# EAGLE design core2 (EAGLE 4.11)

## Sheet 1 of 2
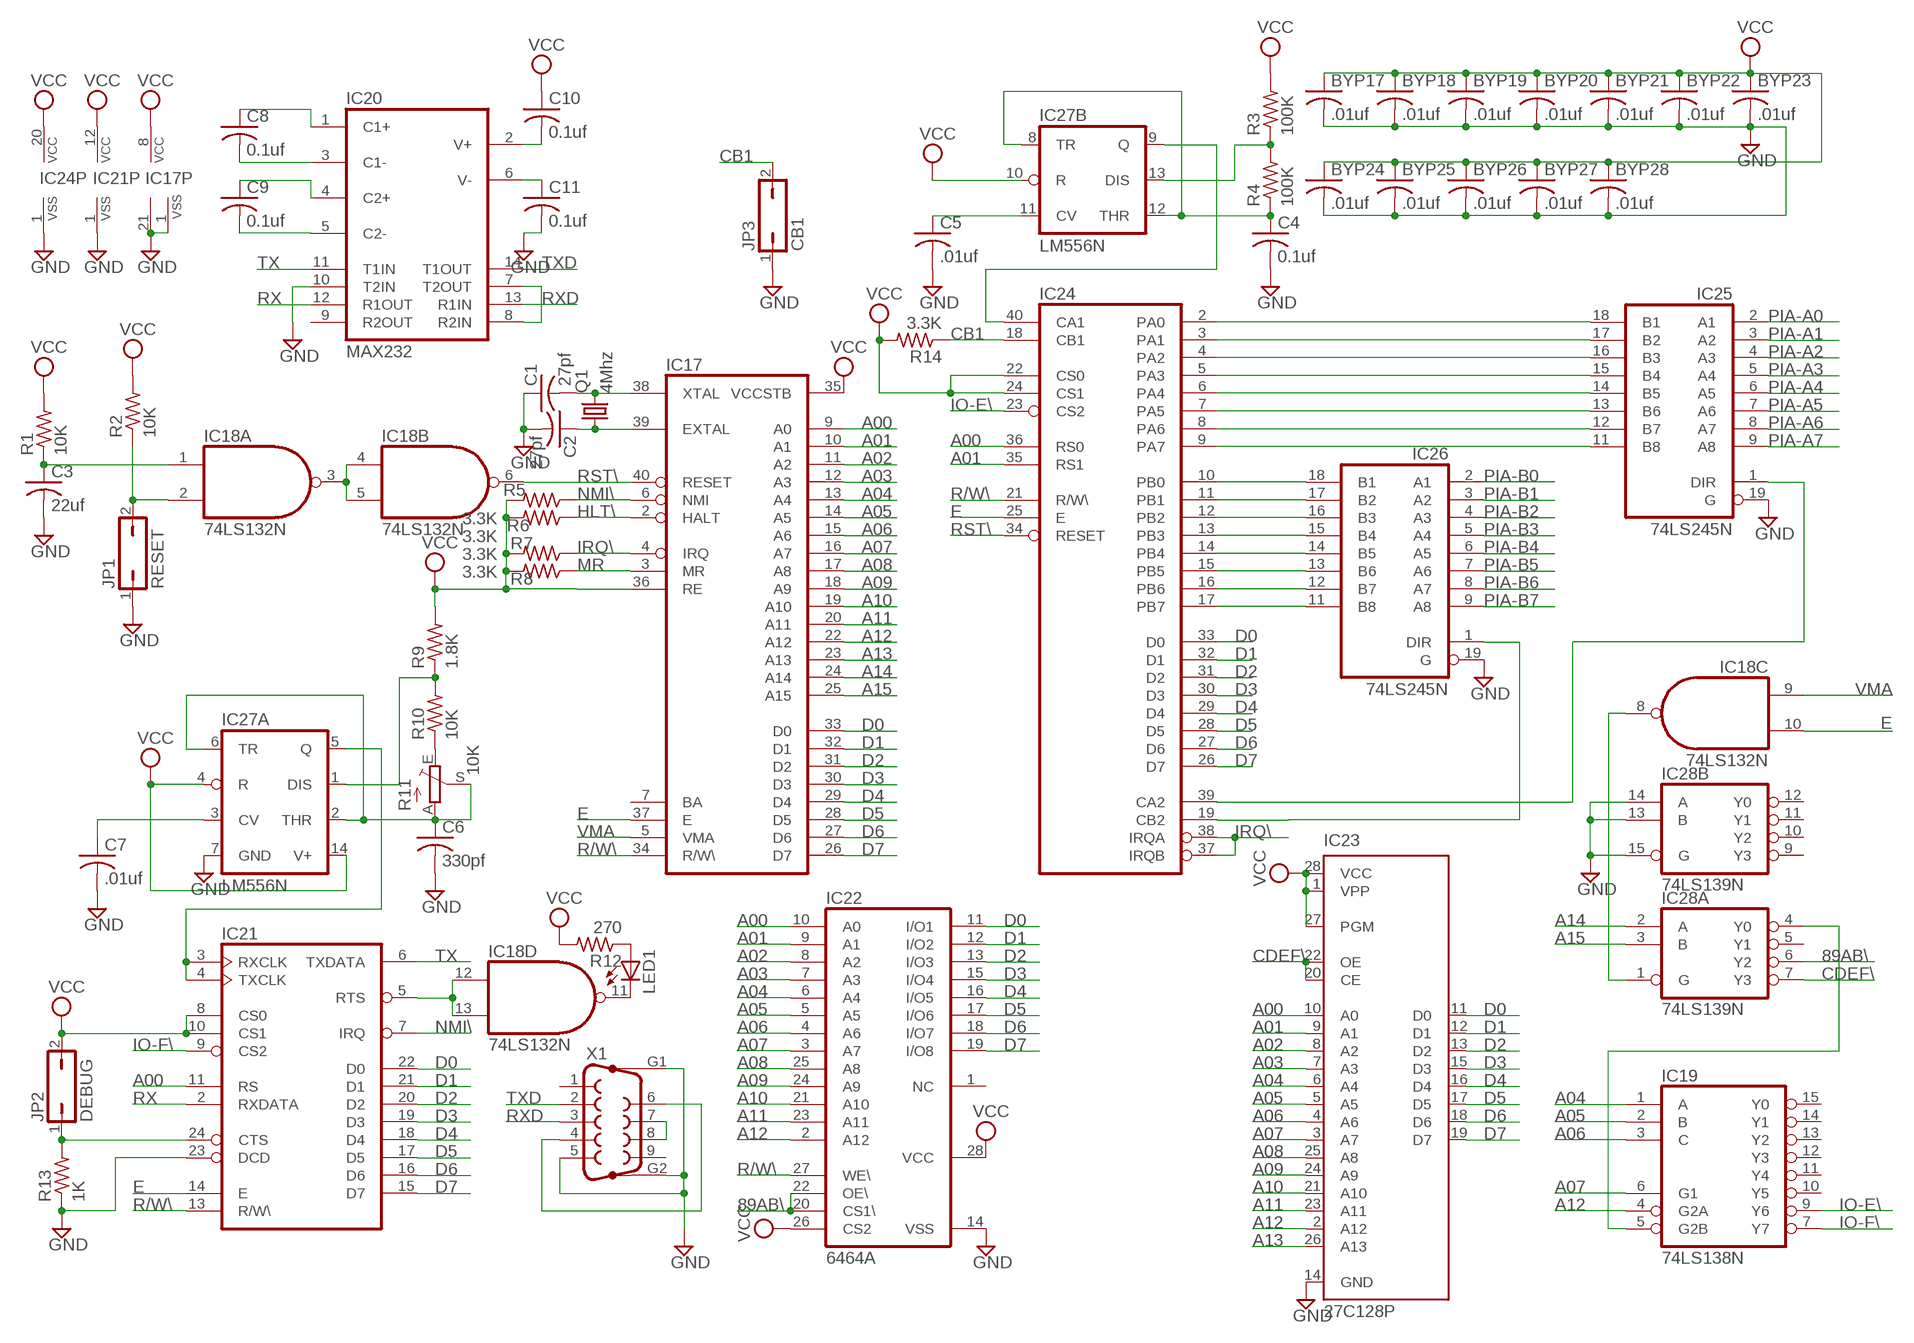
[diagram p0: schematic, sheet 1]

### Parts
BYP17  .01uf  C-US050-025X075  [C050-025X075]
BYP18  .01uf  C-US050-025X075  [C050-025X075]
BYP19  .01uf  C-US050-025X075  [C050-025X075]
BYP20  .01uf  C-US050-025X075  [C050-025X075]
BYP21  .01uf  C-US050-025X075  [C050-025X075]
BYP22  .01uf  C-US050-025X075  [C050-025X075]
BYP23  .01uf  C-US050-025X075  [C050-025X075]
BYP24  .01uf  C-US050-025X075  [C050-025X075]
BYP25  .01uf  C-US050-025X075  [C050-025X075]
BYP26  .01uf  C-US050-025X075  [C050-025X075]
BYP27  .01uf  C-US050-025X075  [C050-025X075]
BYP28  .01uf  C-US050-025X075  [C050-025X075]
C1  27pf  C-US050-025X075  [C050-025X075]
C2  27pf  C-US050-025X075  [C050-025X075]
C3  22uf  C-US102-043X133  [C102-043X133]
C4  0.1uf  C-US050-025X075  [C050-025X075]
C5  .01uf  C-US050-025X075  [C050-025X075]
C6  330pf  C-US050-025X075  [C050-025X075]
C7  .01uf  C-US050-025X075  [C050-025X075]
C8  0.1uf  C-US050-025X075  [C050-025X075]
C9  0.1uf  C-US050-025X075  [C050-025X075]
C10  0.1uf  C-US050-025X075  [C050-025X075]
C11  0.1uf  C-US050-025X075  [C050-025X075]
IC17  6802  [DIL40]
IC18  74LS132N  74LS00N  [DIL14]
IC19  74LS138N  [DIL16]
IC20  MAX232  [DIL16]
IC21  6850  [DIL24]
IC22  6464A  6264A  [DIL28-6]
IC23  27C128P  [DIL28-6]
IC24  6821  [DIL40]
IC25  74LS245N  [DIL20]
IC26  74LS245N  [DIL20]
IC27  LM556N  [DIL14]
IC28  74LS139N  [DIL16]
JP1  RESET  JP1Q  [JP1]
JP2  DEBUG  JP1Q  [JP1]
JP3  CB1  JP1Q  [JP1]
LED1  LED3MM  [LED3MM]
Q1  4Mhz  CRYTALHC18U-V  [HC18U-V]
R1  10K  R-US_0207/7  [0207/7]
R2  10K  R-US_0207/7  [0207/7]
R3  100K  R-US_0207/7  [0207/7]
R4  100K  R-US_0207/7  [0207/7]
R5  3.3K  R-US_0207/7  [0207/7]
R6  3.3K  R-US_0207/7  [0207/7]
R7  3.3K  R-US_0207/7  [0207/7]
R8  3.3K  R-US_0207/7  [0207/7]
R9  1.8K  R-US_0207/7  [0207/7]
R10  10K  R-US_0207/7  [0207/7]
R11  10K  TRIM_EU-B90P  [SP19L]
R12  270  R-US_0207/7  [0207/7]
R13  1K  R-US_0207/7  [0207/7]
R14  3.3K  R-US_0207/7  [0207/7]
X1  F09HP  [F09HP]

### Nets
89AB\: IC22.20(CS1\) IC22.22(OE\) IC28.6(A:Y2)
A00: IC17.9(A0) IC21.11(RS) IC22.10(A0) IC23.10(A0) IC24.36(RS0)
A01: IC17.10(A1) IC22.9(A1) IC23.9(A1) IC24.35(RS1)
A02: IC17.11(A2) IC22.8(A2) IC23.8(A2)
A03: IC17.12(A3) IC22.7(A3) IC23.7(A3)
A04: IC17.13(A4) IC19.1(A) IC22.6(A4) IC23.6(A4)
A05: IC17.14(A5) IC19.2(B) IC22.5(A5) IC23.5(A5)
A06: IC17.15(A6) IC19.3(C) IC22.4(A6) IC23.4(A6)
A07: IC17.16(A7) IC19.6(G1) IC22.3(A7) IC23.3(A7)
A08: IC17.17(A8) IC22.25(A8) IC23.25(A8)
A09: IC17.18(A9) IC22.24(A9) IC23.24(A9)
A10: IC17.19(A10) IC22.21(A10) IC23.21(A10)
A11: IC17.20(A11) IC22.23(A11) IC23.23(A11)
A12: IC17.22(A12) IC19.4(G2A) IC22.2(A12) IC23.2(A12)
A13: IC17.23(A13) IC23.26(A13)
A14: IC17.24(A14) IC28.2(A:A)
A15: IC17.25(A15) IC28.3(A:B)
CB1: IC24.18(CB1) JP3.2 R14.1
CDEF\: IC23.20(CE) IC23.22(OE) IC28.7(A:Y3)
D0: IC17.33(D0) IC21.22(D0) IC22.11(I/O1) IC23.11(D0) IC24.33(D0)
D1: IC17.32(D1) IC21.21(D1) IC22.12(I/O2) IC23.12(D1) IC24.32(D1)
D2: IC17.31(D2) IC21.20(D2) IC22.13(I/O3) IC23.13(D2) IC24.31(D2)
D3: IC17.30(D3) IC21.19(D3) IC22.15(I/O4) IC23.15(D3) IC24.30(D3)
D4: IC17.29(D4) IC21.18(D4) IC22.16(I/O5) IC23.16(D4) IC24.29(D4)
D5: IC17.28(D5) IC21.17(D5) IC22.17(I/O6) IC23.17(D5) IC24.28(D5)
D6: IC17.27(D6) IC21.16(D6) IC22.18(I/O7) IC23.18(D6) IC24.27(D6)
D7: IC17.26(D7) IC21.15(D7) IC22.19(I/O8) IC23.19(D7) IC24.26(D7)
E: IC17.37(E) IC18.10(C:I1) IC21.14(E) IC24.25(E)
GND [Power]: BYP17.2 BYP18.2 BYP19.2 BYP20.2 BYP21.2 BYP22.2 BYP23.2 BYP24.2 BYP25.2 BYP26.2 BYP27.2 BYP28.2 C1.1 C2.2 C3.2 C4.2 C5.2 C6.2 C7.2 C11.2 IC17.1(VSS) IC17.21(VSS) IC20.10(T2IN) IC21.1(VSS) IC21.23(DCD) IC22.14(VSS) IC23.14(GND) IC24.1(VSS) IC25.19(G) IC26.19(G) IC27.7(A:GND) IC28.13(B:B) IC28.14(B:A) IC28.15(B:G) JP1.1 JP3.1 R13.1 X1.5 X1.G1 X1.G2 ; also sheet 2
HLT\: IC17.2(HALT) R5.1
IO-E\: IC19.9(Y6) IC24.23(CS2)
IO-F\: IC19.7(Y7) IC21.9(CS2)
IRQ\: IC17.4(IRQ) IC24.37(IRQB) IC24.38(IRQA) R7.1
MR: IC17.3(MR) R8.1
N$3: C2.1 IC17.39(EXTAL) Q1.1
N$4: C1.2 IC17.38(XTAL) Q1.2
N$5: IC24.2(PA0) IC25.18(B1)
N$6: IC18.3(A:O) IC18.4(B:I0) IC18.5(B:I1)
N$21: C3.1 IC18.1(A:I0) R1.1
N$22: IC18.2(A:I1) JP1.2 R2.1
N$23: IC21.3(RXCLK) IC21.4(TXCLK) IC27.5(A:Q)
N$24: IC24.10(PB0) IC26.18(B1)
N$25: IC24.11(PB1) IC26.17(B2)
N$27: C6.1 IC27.2(A:THR) IC27.6(A:TR) R11.A R11.S
N$28: IC27.1(A:DIS) R9.1 R10.2
N$94: IC24.12(PB2) IC26.16(B3)
N$124: IC24.13(PB3) IC26.15(B4)
N$125: IC24.14(PB4) IC26.14(B5)
N$126: IC24.15(PB5) IC26.13(B6)
N$127: IC24.16(PB6) IC26.12(B7)
N$128: IC24.17(PB7) IC26.11(B8)
N$129: IC24.3(PA1) IC25.17(B2)
N$130: IC24.4(PA2) IC25.16(B3)
N$131: IC24.5(PA3) IC25.15(B4)
N$132: IC24.6(PA4) IC25.14(B5)
N$133: IC24.7(PA5) IC25.13(B6)
N$134: IC24.8(PA6) IC25.12(B7)
N$135: IC24.9(PA7) IC25.11(B8)
N$136: IC24.19(CB2) IC26.1(DIR)
N$137: IC24.39(CA2) IC25.1(DIR)
N$138: IC24.40(CA1) IC27.9(B:Q)
N$140: C4.1 IC27.8(B:TR) IC27.12(B:THR) R4.1
N$141: IC27.13(B:DIS) R3.1 R4.2
N$142: C5.1 IC27.11(B:CV)
N$143: R10.1 R11.E
N$144: X1.4 X1.6
N$145: X1.7 X1.8
N$147: IC18.12(D:I0) IC18.13(D:I1) IC21.5(RTS)
N$148: IC18.11(D:O) LED1.K(C)
N$149: LED1.A R12.1
N$150: IC21.24(CTS) JP2.1 R13.2
N$151: IC18.8(C:O) IC28.1(A:G)
N$152: IC19.5(G2B) IC28.4(A:Y0)
N$153: IC20.7(T2OUT) IC20.8(R2IN)
N$154: C7.1 IC27.3(A:CV)
N$155: C9.2 IC20.5(C2-)
N$156: C9.1 IC20.4(C2+)
N$157: C8.2 IC20.3(C1-)
N$158: C8.1 IC20.1(C1+)
N$159: C11.1 IC20.6(V-)
N$160: C10.2 IC20.2(V+)
NMI\: IC17.6(NMI) IC21.7(IRQ) R6.1
PIA-A0: IC25.2(A1) ; also sheet 2
PIA-A1: IC25.3(A2) ; also sheet 2
PIA-A2: IC25.4(A3) ; also sheet 2
PIA-A3: IC25.5(A4) ; also sheet 2
PIA-A4: IC25.6(A5) ; also sheet 2
PIA-A5: IC25.7(A6) ; also sheet 2
PIA-A6: IC25.8(A7) ; also sheet 2
PIA-A7: IC25.9(A8) ; also sheet 2
PIA-B0: IC26.2(A1) ; also sheet 2
PIA-B1: IC26.3(A2) ; also sheet 2
PIA-B2: IC26.4(A3) ; also sheet 2
PIA-B3: IC26.5(A4) ; also sheet 2
PIA-B4: IC26.6(A5) ; also sheet 2
PIA-B5: IC26.7(A6) ; also sheet 2
PIA-B6: IC26.8(A7) ; also sheet 2
PIA-B7: IC26.9(A8) ; also sheet 2
R/W\: IC17.34(R/W\) IC21.13(R/W\) IC22.27(WE\) IC24.21(R/W\)
RST\: IC17.40(RESET) IC18.6(B:O) IC24.34(RESET)
RX: IC20.12(R1OUT) IC21.2(RXDATA)
RXD: IC20.13(R1IN) X1.3
TX: IC20.11(T1IN) IC21.6(TXDATA)
TXD: IC20.14(T1OUT) X1.2
VCC [Power]: BYP17.1 BYP18.1 BYP19.1 BYP20.1 BYP21.1 BYP22.1 BYP23.1 BYP24.1 BYP25.1 BYP26.1 BYP27.1 BYP28.1 C10.1 IC17.8(VCC) IC17.35(VCCSTB) IC17.36(RE) IC21.8(CS0) IC21.10(CS1) IC21.12(VCC) IC22.26(CS2) IC22.28(VCC) IC23.1(VPP) IC23.27(PGM) IC23.28(VCC) IC24.20(VCC) IC24.22(CS0) IC24.24(CS1) IC27.4(A:R) IC27.10(B:R) IC27.14(A:V+) JP2.2 R1.2 R2.2 R3.2 R5.2 R6.2 R7.2 R8.2 R9.2 R12.2 R14.2 ; also sheet 2
VMA: IC17.5(VMA) IC18.9(C:I0)
Unconnected: IC17.7(BA) IC19.10(Y5) IC19.11(Y4) IC19.12(Y3) IC19.13(Y2) IC19.14(Y1) IC19.15(Y0) IC20.9(R2OUT) IC22.1(NC) IC28.5(A:Y1) IC28.9(B:Y3) IC28.10(B:Y2) IC28.11(B:Y1) IC28.12(B:Y0) X1.1 X1.9

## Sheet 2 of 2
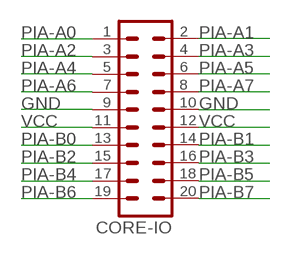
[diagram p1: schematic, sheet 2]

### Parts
CORE-IO  MA10-2  [MA10-2]

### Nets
GND [Power]: CORE-IO.9 CORE-IO.10 ; also sheet 1
PIA-A0: CORE-IO.1 ; also sheet 1
PIA-A1: CORE-IO.2 ; also sheet 1
PIA-A2: CORE-IO.3 ; also sheet 1
PIA-A3: CORE-IO.4 ; also sheet 1
PIA-A4: CORE-IO.5 ; also sheet 1
PIA-A5: CORE-IO.6 ; also sheet 1
PIA-A6: CORE-IO.7 ; also sheet 1
PIA-A7: CORE-IO.8 ; also sheet 1
PIA-B0: CORE-IO.13 ; also sheet 1
PIA-B1: CORE-IO.14 ; also sheet 1
PIA-B2: CORE-IO.15 ; also sheet 1
PIA-B3: CORE-IO.16 ; also sheet 1
PIA-B4: CORE-IO.17 ; also sheet 1
PIA-B5: CORE-IO.18 ; also sheet 1
PIA-B6: CORE-IO.19 ; also sheet 1
PIA-B7: CORE-IO.20 ; also sheet 1
VCC [Power]: CORE-IO.11 CORE-IO.12 ; also sheet 1

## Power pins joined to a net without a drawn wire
GND: IC18.7(P:GND) IC19.8(GND) IC20.15(GND) IC25.10(GND) IC26.10(GND) IC28.8(P:GND)
VCC: IC18.14(P:VCC) IC19.16(VCC) IC20.16(VCC) IC25.20(VCC) IC26.20(VCC) IC28.16(P:VCC)

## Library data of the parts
BYP17-BYP28 C1-C11 = rcl:C-US: CAPACITOR, American symbol
CORE-IO = con-lstb:MA10-2: PIN HEADER
IC17 = micro-motorola:6802: MICROCONTROLLER/MEMORY DEVICE
IC18 = 74xx-us:74*00: Quad 2-input NAND gate
IC19 = 74xx-us:74*138: 3-line to 8-line DECODER/DEMULTIPLEXER
IC20 = maxim:MAX232: RS232 TRANSEIVER
IC21 = micro-motorola:6850: MICROCONTROLLER/MEMORY DEVICE
IC22 = memory-hitachi:6264A: MEMORY
IC23 = microchip:27*128: CMOS EPROM 128 K (16 K x 8)
IC24 = micro-motorola:6821: MICROCONTROLLER/MEMORY DEVICE
IC25 IC26 = 74xx-us:74*245: Octal BUS TRANSCEIVER, 3-state
IC27 = linear:*556: Dual TIMER
IC28 = 74xx-us:74*139: Dual 2-line to 4-line DECODER/DEMULTIPLEXER
JP1-JP3 = jumper:JP1Q: JUMPER
LED1 = led:LED: LED
Q1 = crystal:CRYTAL: CRYSTAL
R1-R10 R12-R14 = rcl:R-US_: RESISTOR, American symbol
R11 = pot:TRIM_EU-: POTENTIOMETER
X1 = con-subd:F09HP: SUB-D

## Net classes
1 Power: width 0.508 mm, drill 0.254 mm, clearance 0.254 mm

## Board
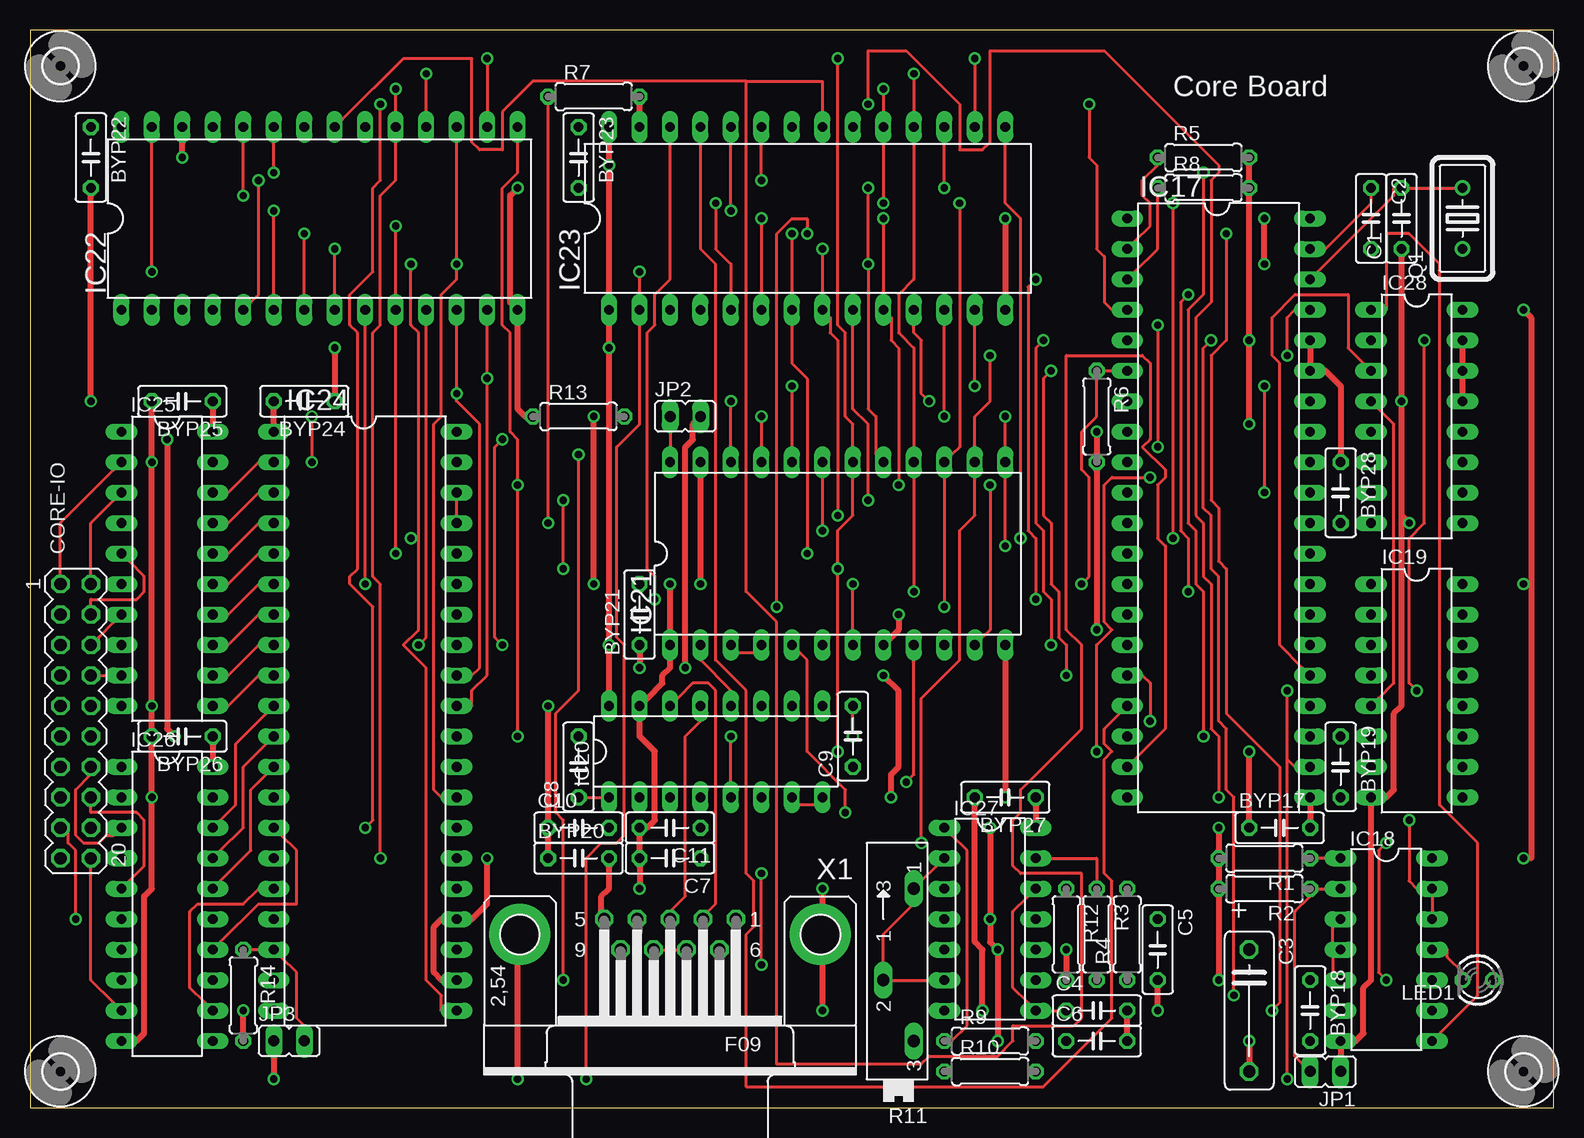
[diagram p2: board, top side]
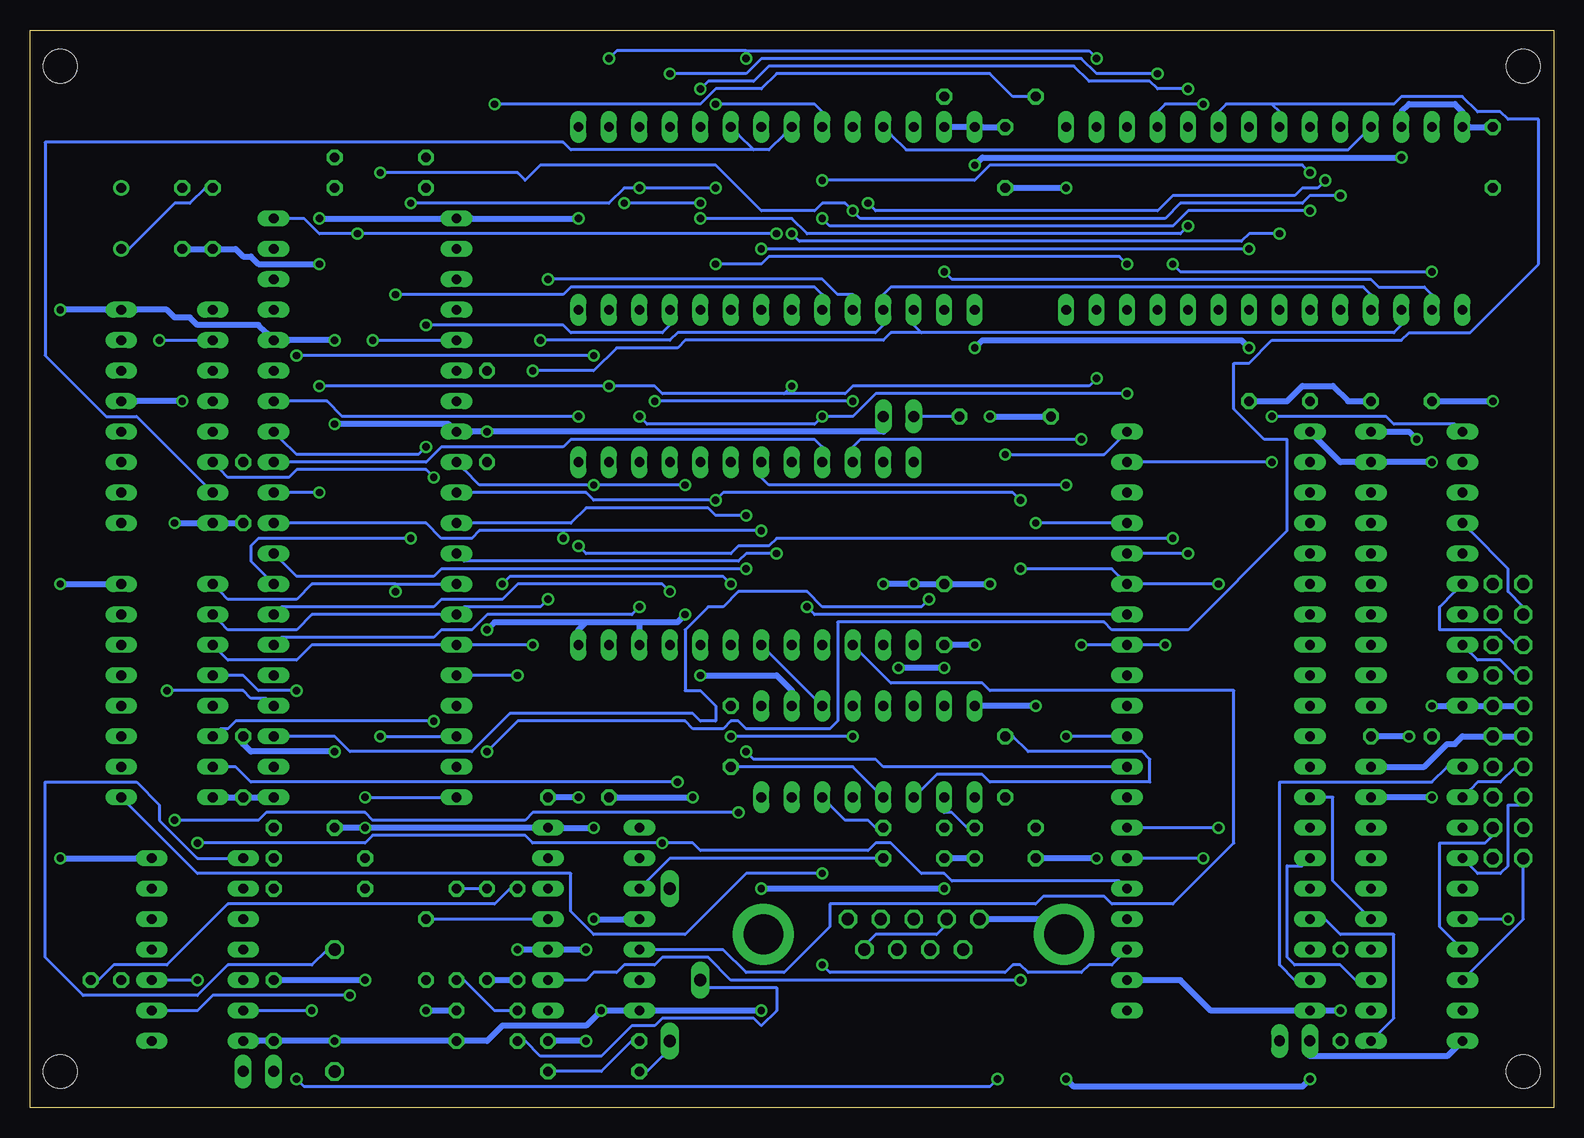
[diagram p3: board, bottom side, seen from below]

Size 126.98 x 89.84 mm. Coordinates in mm from the lower left corner, seen from the top.
Outline: 0,0 126.98,0 126.98,89.84 0,89.84 0,0
Copper layers (1*16): Top 0.035mm / dielectric 1.5mm / Bottom 0.035mm
Design rules "default": minimum track width 10mil, minimum drill 24mil, track to track 8mil, track to pad 8mil, pad to pad 8mil, via to via 8mil, smd to smd 8mil, copper to edge 40mil, drill to drill 8mil, minimum pad ring 10mil, minimum via ring 8mil, stop-mask expansion 4mil, vias tented up to drill 0mil, thermal gap 10mil

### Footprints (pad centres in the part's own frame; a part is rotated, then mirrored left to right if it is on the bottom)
C050-025X075 = drill 0.813 octagon: 1 -2.54,0; 2 2.54,0
C102-043X133 = drill 1.016 octagon: 1 -5.08,0; 2 5.08,0
MA10-2 = drill 1.016 octagon: 1 -11.43,-1.27; 2 -11.43,1.27; 3 -8.89,-1.27; 4 -8.89,1.27; 5 -6.35,-1.27; 6 -6.35,1.27; 7 -3.81,-1.27; 8 -3.81,1.27; 9 -1.27,-1.27; 10 -1.27,1.27; 11 1.27,-1.27; 12 1.27,1.27; 13 3.81,-1.27; 14 3.81,1.27; 15 6.35,-1.27; 16 6.35,1.27; 17 8.89,-1.27; 18 8.89,1.27; 19 11.43,-1.27; 20 11.43,1.27
DIL40 = drill 0.813 long: 1 -24.13,-7.62; 2 -21.59,-7.62; 3 -19.05,-7.62; 4 -16.51,-7.62; 5 -13.97,-7.62; 6 -11.43,-7.62; 7 -8.89,-7.62; 8 -6.35,-7.62; 9 -3.81,-7.62; 10 -1.27,-7.62; 11 1.27,-7.62; 12 3.81,-7.62; 13 6.35,-7.62; 14 8.89,-7.62; 15 11.43,-7.62; 16 13.97,-7.62; 17 16.51,-7.62; 18 19.05,-7.62; 19 21.59,-7.62; 20 24.13,-7.62; 21 24.13,7.62; 22 21.59,7.62; 23 19.05,7.62; 24 16.51,7.62; 25 13.97,7.62; 26 11.43,7.62; 27 8.89,7.62; 28 6.35,7.62; 29 3.81,7.62; 30 1.27,7.62; 31 -1.27,7.62; 32 -3.81,7.62; 33 -6.35,7.62; 34 -8.89,7.62; 35 -11.43,7.62; 36 -13.97,7.62; 37 -16.51,7.62; 38 -19.05,7.62; 39 -21.59,7.62; 40 -24.13,7.62
DIL14 = drill 0.813 long: 1 -7.62,-3.81; 2 -5.08,-3.81; 3 -2.54,-3.81; 4 0,-3.81; 5 2.54,-3.81; 6 5.08,-3.81; 7 7.62,-3.81; 8 7.62,3.81; 9 5.08,3.81; 10 2.54,3.81; 11 0,3.81; 12 -2.54,3.81; 13 -5.08,3.81; 14 -7.62,3.81
DIL16 = drill 0.813 long: 1 -8.89,-3.81; 2 -6.35,-3.81; 3 -3.81,-3.81; 4 -1.27,-3.81; 5 1.27,-3.81; 6 3.81,-3.81; 7 6.35,-3.81; 8 8.89,-3.81; 9 8.89,3.81; 10 6.35,3.81; 11 3.81,3.81; 12 1.27,3.81; 13 -1.27,3.81; 14 -3.81,3.81; 15 -6.35,3.81; 16 -8.89,3.81
DIL24 = drill 0.813 long: 1 -13.97,-7.62; 2 -11.43,-7.62; 3 -8.89,-7.62; 4 -6.35,-7.62; 5 -3.81,-7.62; 6 -1.27,-7.62; 7 1.27,-7.62; 8 3.81,-7.62; 9 6.35,-7.62; 10 8.89,-7.62; 11 11.43,-7.62; 12 13.97,-7.62; 13 13.97,7.62; 14 11.43,7.62; 15 8.89,7.62; 16 6.35,7.62; 17 3.81,7.62; 18 1.27,7.62; 19 -1.27,7.62; 20 -3.81,7.62; 21 -6.35,7.62; 22 -8.89,7.62; 23 -11.43,7.62; 24 -13.97,7.62
DIL28-6 = drill 0.813 long: 1 -16.51,-7.62; 2 -13.97,-7.62; 3 -11.43,-7.62; 4 -8.89,-7.62; 5 -6.35,-7.62; 6 -3.81,-7.62; 7 -1.27,-7.62; 8 1.27,-7.62; 9 3.81,-7.62; 10 6.35,-7.62; 11 8.89,-7.62; 12 11.43,-7.62; 13 13.97,-7.62; 14 16.51,-7.62; 15 16.51,7.62; 16 13.97,7.62; 17 11.43,7.62; 18 8.89,7.62; 19 6.35,7.62; 20 3.81,7.62; 21 1.27,7.62; 22 -1.27,7.62; 23 -3.81,7.62; 24 -6.35,7.62; 25 -8.89,7.62; 26 -11.43,7.62; 27 -13.97,7.62; 28 -16.51,7.62
DIL20 = drill 0.813 long: 1 -11.43,-3.81; 2 -8.89,-3.81; 3 -6.35,-3.81; 4 -3.81,-3.81; 5 -1.27,-3.81; 6 1.27,-3.81; 7 3.81,-3.81; 8 6.35,-3.81; 9 8.89,-3.81; 10 11.43,-3.81; 11 11.43,3.81; 12 8.89,3.81; 13 6.35,3.81; 14 3.81,3.81; 15 1.27,3.81; 16 -1.27,3.81; 17 -3.81,3.81; 18 -6.35,3.81; 19 -8.89,3.81; 20 -11.43,3.81
JP1 = drill 0.914 long: 1 0,-1.27; 2 0,1.27
LED3MM = drill 0.813 octagon: A -1.27,0; K 1.27,0
HC18U-V = drill 0.813 round: 1 -2.54,0; 2 2.54,0
0207/7 = drill 0.813 octagon: 1 -3.81,0; 2 3.81,0
SP19L = drill 1.016 long: A 5.715,-1.27; E -6.985,-1.27; S -1.905,1.27
2,8 = hole 2.8: 0,0
F09HP = drill 1.016 octagon: 1 -5.486,-1.27; 2 -2.743,-1.27; 3 0,-1.27; 4 2.743,-1.27; 5 5.486,-1.27; 6 -4.115,1.27; 7 -1.372,1.27; 8 1.372,1.27; 9 4.115,1.27 | drill 3.302 pad 5.08 round: G1 -12.522,0; G2 12.522,0

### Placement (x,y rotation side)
BYP17  104.14,23.33 0 top
BYP18  106.68,8.09 270 top
BYP19  109.22,28.41 270 top
BYP20  45.71,20.79 0 top
BYP21  50.79,41.11 90 top
BYP22  5.08,79.21 270 top
BYP23  45.71,79.21 270 top
BYP24  22.86,58.89 180 top
BYP25  12.69,58.89 180 top
BYP26  12.69,30.95 180 top
BYP27  81.28,25.87 180 top
BYP28  109.22,51.27 270 top
C1  114.3,74.13 90 top
C2  111.76,74.13 270 top
C3  101.59,8.09 270 top
C4  88.9,8.09 0 top
C5  93.98,13.17 270 top
C6  88.9,5.55 0 top
C7  53.34,20.79 180 top
C8  45.71,28.41 90 top
C9  68.58,30.95 90 top
C10  45.71,23.33 0 top
C11  53.34,23.33 180 top
CORE-IO  3.81,32.22 270 top
IC17  99.06,50 270 top
IC18  113.03,13.17 270 top
IC19  115.56,34.76 270 top
IC20  57.14,29.68 0 top
IC21  67.31,46.19 0 top
IC22  24.12,74.13 0 top
IC23  64.77,74.13 0 top
IC24  27.94,32.22 270 top
IC25  11.42,44.92 270 top
IC26  11.42,16.98 270 top
IC27  80.01,15.71 270 top
IC28  115.56,57.62 270 top
JP1  107.95,3.01 90 top
JP2  54.6,57.62 270 top
JP3  21.59,5.55 270 top
LED1  120.65,10.63 180 top
Q1  119.38,74.13 90 top
R1  102.87,20.79 180 top
R2  102.87,18.25 180 top
R3  88.9,14.44 270 top
R4  91.44,14.44 90 top
R5  97.79,79.21 0 top
R6  88.9,57.62 270 top
R7  46.98,84.29 0 top
R8  97.79,76.67 0 top
R9  80.01,5.55 0 top
R10  80.01,3.01 0 top
R11  72.39,12.54 90 top
R12  86.36,14.44 270 top
R13  45.71,57.62 0 top
R14  17.78,9.36 270 top
U$3  [2,8]  2.54,86.83 0 top
U$4  [2,8]  2.54,3.01 0 top
U$5  [2,8]  124.45,86.83 0 top
U$6  [2,8]  124.45,3.01 0 top
X1  53.34,14.44 180 top

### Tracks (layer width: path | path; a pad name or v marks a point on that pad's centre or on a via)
89AB\  (via drill 0.61)
  Top 0.254: v93.34,52.54 90.17,52.54 89.53,51.91 89.53,40.48 90.17,39.84 88.9,38.57 v88.9,29.68
  Bottom 0.254: 23.49,83.66 27.3,83.66 27.94,83.02 IC22.20 | 23.49,83.66 22.86,83.02 IC22.22 | v93.34,52.54 93.98,53.17 104.77,53.17 105.41,52.54 110.48,52.54 111.12,53.17 IC28.6 | v88.9,29.68 86.36,32.22 72.39,32.22 71.75,31.58 69.21,31.58 68.58,32.22 67.94,32.22 67.31,31.58 60.32,31.58 59.68,32.22 59.68,40.48 37.46,40.48 36.82,39.84 30.48,39.84 22.22,48.09 22.22,55.71 24.12,55.71 26.67,58.25 26.67,62.06 25.39,62.06 23.49,63.97 12.69,63.97 12.06,64.61 6.98,64.61 1.27,70.32 1.27,82.39 3.81,82.39 4.44,83.02 6.34,83.02 7.62,84.29 12.69,84.29 13.33,83.66 23.49,83.66
A00  (via drill 0.61)
  Top 0.254: v30.48,46.19 30.48,65.24 IC22.10 30.48,67.78 v30.48,73.5 | v80.01,51.91 80.01,39.84 79.37,39.2 IC21.11 | v72.39,51.91 72.39,63.34 71.75,63.97 71.75,65.88 IC23.10 71.12,67.78 v71.12,74.13
  Bottom 0.254: v30.48,46.19 34.28,46.19 IC24.36 | IC17.9 90.8,53.17 89.53,51.91 v80.01,51.91 v72.39,51.91 | v30.48,73.5 31.11,72.86 62.22,72.86 63.49,74.13 v71.12,74.13
A01  (via drill 0.61)
  Top 0.254: v27.94,43.65 27.94,65.24 IC22.9 | v69.84,50.63 69.84,56.98 68.58,58.25 68.58,65.24 IC23.9 | v44.45,44.92 v44.45,50.63
  Bottom 0.254: v27.94,43.65 34.28,43.65 IC24.35 36.19,44.28 36.82,44.92 v44.45,44.92 | IC17.10 90.17,51.27 80.64,51.27 80.01,50.63 v69.84,50.63 69.21,51.27 45.08,51.27 v44.45,50.63
A02  (via drill 0.61)
  Top 0.254: v25.39,71.59 25.39,67.78 IC22.8 | v66.04,71.59 66.04,67.78 IC23.8 66.67,65.88 66.67,64.61 67.31,63.97 v67.31,49.37
  Bottom 0.254: v25.39,71.59 v66.04,71.59 | v67.31,49.37 69.84,49.37 70.48,50 80.64,50 81.91,48.73 90.17,48.73 IC17.11
A03  (via drill 0.61)
  Top 0.254: v22.86,72.86 22.86,67.78 IC22.7 | v63.49,72.86 63.49,67.78 IC23.7 63.49,65.24 63.49,62.06 64.77,60.8 v64.77,46.19
  Bottom 0.254: v22.86,72.86 25.39,72.86 26.03,72.22 62.86,72.22 v63.49,72.86 | v64.77,46.19 67.31,46.19 67.94,45.55 90.8,45.55 IC17.12
A04  (via drill 0.61)
  Top 0.254: v20.32,74.77 20.32,67.78 IC22.6 | v60.95,74.13 60.95,67.78 IC23.6 | v96.52,43.02 96.52,47.46 95.88,48.09 95.88,67.14 v96.52,67.78
  Bottom 0.254: 96.52,43.65 92.7,43.65 IC17.13 | 96.52,43.65 103.5,43.65 104.77,42.38 110.48,42.38 111.12,43.02 IC19.1 | v20.32,74.77 30.48,74.77 31.75,73.5 60.32,73.5 v60.95,74.13 | v96.52,43.02 96.52,43.65 | v96.52,67.78 82.55,67.78 81.91,68.41 61.59,68.41 60.95,67.78 IC23.6
A05  (via drill 0.61)
  Top 0.254: v19.05,77.3 19.05,67.78 18.41,67.14 IC22.5 | v57.14,75.4 57.14,71.59 58.41,70.32 58.41,67.78 IC23.5 | v83.81,42.38 83.81,47.46 83.18,48.09 83.18,68.41 v83.81,69.05
  Bottom 0.254: IC19.2 111.12,40.48 110.48,39.84 104.77,39.84 103.5,41.11 92.7,41.11 IC17.14 90.8,41.74 84.45,41.74 v83.81,42.38 | v19.05,77.3 19.68,76.67 20.95,76.67 21.59,76.03 31.75,76.03 33.02,74.77 56.51,74.77 v57.14,75.4 | v83.81,69.05 60.95,69.05 59.68,67.78 58.41,67.78 IC23.5
A06  (via drill 0.61)
  Top 0.254: v85.09,38.57 85.09,42.38 84.45,43.02 84.45,48.09 83.81,48.73 83.81,63.34 v84.45,63.97
  Bottom 0.254: IC19.3 111.12,37.94 110.48,37.3 104.77,37.3 103.5,38.57 92.7,38.57 IC17.15 90.17,38.57 v85.09,38.57 | IC22.4 15.23,67.78 15.87,68.41 55.24,68.41 55.88,67.78 IC23.4 55.88,65.24 56.51,64.61 73.02,64.61 73.66,63.97 v84.45,63.97
A07  (via drill 0.61)
  Top 0.254: v93.34,32.22 93.34,35.39 92.7,36.03 IC17.16 | v86.36,36.03 86.36,38.57 85.72,39.2 85.72,43.02 85.09,43.65 85.09,48.73 84.45,49.37 84.45,60.8 v85.09,61.43
  Bottom 0.254: v93.34,32.22 109.85,32.22 110.48,31.58 111.12,31.58 IC19.6 | 52.7,64.61 53.34,65.24 IC23.3 | 52.7,64.61 13.33,64.61 12.69,65.24 IC22.3 | v86.36,36.03 90.17,36.03 IC17.16 | v85.09,61.43 80.01,61.43 78.1,63.34 73.02,63.34 72.39,63.97 55.88,63.97 55.24,64.61 52.7,64.61
A08
  Top 0.254: IC17.17 90.8,32.85 89.53,31.58 89.53,30.31 90.17,29.68 89.53,29.04 89.53,19.52 90.17,18.88 90.17,7.46 84.45,1.74 59.68,1.74 59.68,14.44 60.32,15.08 60.32,18.88 59.68,19.52 59.68,34.76 57.14,37.3 57.14,70.32 55.88,71.59 55.88,80.48 IC23.25
  Bottom 0.254: IC22.25 15.87,81.11 17.14,79.84 53.97,79.84 55.24,81.11 IC23.25
A09  (via drill 0.61)
  Top 0.254: v17.78,76.03 17.78,80.48 IC22.24 | v58.41,74.77 58.41,80.48 IC23.24 | v97.79,30.95 97.79,43.02 97.15,43.65 97.15,48.09 96.52,48.73 96.52,66.51 97.79,67.78 v97.79,77.94
  Bottom 0.254: v17.78,76.03 20.32,76.03 20.95,75.4 31.11,75.4 32.38,74.13 57.78,74.13 v58.41,74.77 59.05,75.4 60.95,75.4 61.59,74.77 66.04,74.77 69.84,78.58 84.45,78.58 85.72,77.3 86.36,77.94 v97.79,77.94 | v97.79,30.95 92.7,30.95 IC17.18
A10
  Top 0.254: 59.68,85.56 66.04,85.56 66.04,83.02 IC23.21 | 59.68,85.56 41.9,85.56 39.36,83.02 39.36,79.84 37.46,79.84 36.82,80.48 36.82,87.47 31.11,87.47 26.03,82.39 IC22.21 | 59.68,85.56 59.68,43.02 62.22,40.48 62.22,3.64 74.29,3.64 74.93,4.28 80.64,4.28 81.91,5.55 81.91,6.82 86.99,6.82 87.62,7.46 87.62,19.52 82.55,19.52 81.91,20.15 81.91,23.96 82.55,24.6 82.55,26.5 87.62,31.58 87.62,38.57 86.36,39.84 86.36,62.7 92.7,62.7 93.34,62.06 93.34,55.71 92.7,55.08 94.61,53.17 94.61,52.54 93.98,51.91 93.98,47.46 94.61,46.82 94.61,31.58 92.07,29.04 IC17.19
A11  (via drill 0.61)
  Top 0.254: v20.32,77.94 20.32,80.48 IC22.23 | v60.95,77.3 60.95,80.48 IC23.23 | v99.06,25.87 99.06,30.95 98.42,31.58 98.42,43.65 97.79,44.28 97.79,48.73 97.15,49.37 97.15,65.88 98.42,67.14 98.42,77.3 99.06,77.94 99.06,78.58 89.53,88.1 80.01,88.1 80.01,80.48 79.37,79.84 77.47,79.84 77.47,83.66 73.02,88.1 69.84,88.1 v69.84,83.66
  Bottom 0.254: v20.32,77.94 20.95,78.58 46.98,78.58 48.25,77.3 v60.95,77.3 | v99.06,25.87 92.7,25.87 IC17.20 | v69.84,83.66 61.59,83.66 60.95,83.02 IC23.23
A12  (via drill 0.61)
  Top 0.254: 104.77,29.04 105.41,28.41 IC17.22 | 104.77,29.04 v104.77,34.76 | v50.79,69.69 50.79,67.78 IC23.2 50.79,65.24 50.79,56.98 48.89,55.08 48.89,39.2 49.52,38.57 49.52,22.7 48.89,22.06 47.62,22.06 46.35,20.79 v46.35,2.38 | v104.77,2.38 104.77,29.04
  Bottom 0.254: v104.77,34.76 107.95,34.76 109.22,36.03 110.48,36.03 IC19.4 | v50.79,69.69 50.16,69.05 15.23,69.05 14.6,68.41 10.79,68.41 10.15,67.78 IC22.2 | v104.77,2.38 104.14,1.74 46.98,1.74 v46.35,2.38
A13  (via drill 0.61)
  Top 0.254: v52.06,42.38 52.06,44.28 51.43,44.92 51.43,64.61 52.06,65.24 52.06,67.78 53.34,69.05 53.34,80.48 IC23.26
  Bottom 0.254: v52.06,42.38 52.7,41.74 60.95,41.74 62.22,43.02 67.94,43.02 69.21,41.74 70.48,41.74 72.39,39.84 72.39,34.76 71.12,34.76 69.84,33.49 69.84,32.22 71.12,32.22 71.75,32.85 86.99,32.85 90.17,29.68 100.33,29.68 101.59,30.95 105.41,30.95 IC17.23
A14  (via drill 0.61)
  Top 0.254: v115.56,34.76 114.93,35.39 114.93,47.46 116.2,48.73 v116.2,63.97
  Bottom 0.254: v115.56,34.76 109.22,34.76 108.58,34.12 107.31,34.12 IC17.24 | v116.2,63.97 113.03,63.97 IC28.2
A15
  Top 0.254: IC17.25 106.04,36.66 104.14,38.57 104.14,62.06 103.5,62.7 103.5,65.88 105.41,67.78 109.85,67.78 109.85,63.34 111.12,62.06 IC28.3
CB1
  Top 0.254: R14.1 18.41,13.17 19.05,13.17 IC24.18 20.95,12.54 22.22,11.27 22.22,7.46 22.86,6.82 JP3.2
CDEF\
  Bottom 0.254: 66.67,79.84 65.4,79.84 64.13,81.11 IC23.22 | 66.67,79.84 67.94,81.11 IC23.20 | 66.67,79.84 81.91,79.84 82.55,80.48 125.73,80.48 125.73,62.7 120.65,57.62 118.11,57.62 112.39,51.91 IC28.7
D0  (via drill 0.61)
  Top 0.254: v32.38,38.57 33.02,39.2 33.02,65.24 IC22.11 | v58.41,58.89 58.41,55.08 IC21.22 | v74.93,58.89 74.29,59.52 74.29,63.97 73.66,64.61 73.66,65.24 IC23.11 | v93.98,65.24 v93.98,55.08 | v39.36,38.57 38.73,39.2 38.73,55.08 v39.36,55.71
  Bottom 0.254: v32.38,38.57 34.28,38.57 IC24.33 36.82,38.57 v39.36,38.57 | v58.41,58.89 v74.93,58.89 | v93.98,55.08 94.61,54.45 104.77,54.45 106.04,55.71 IC17.33 | v93.98,65.24 82.55,65.24 81.91,64.61 74.29,64.61 73.66,65.24 IC23.11 | v39.36,55.71 57.78,55.71 58.41,55.08 IC21.22
D1  (via drill 0.61)
  Top 0.254: IC22.12 35.55,65.24 v35.55,59.52 35.55,58.89 37.46,56.98 37.46,36.66 36.82,36.03 IC24.32 | v76.2,57.62 76.2,65.24 IC23.12 | v60.95,57.62 60.95,55.08 IC21.21
  Bottom 0.254: IC17.32 105.41,53.81 93.98,53.81 92.7,55.08 82.55,55.08 81.91,55.71 61.59,55.71 60.95,55.08 IC21.21 | v76.2,57.62 75.56,56.98 61.59,56.98 v60.95,57.62 58.41,57.62 56.51,59.52 v35.55,59.52
D2  (via drill 0.61)
  Top 0.254: IC24.31 36.82,33.49 36.82,34.76 38.09,36.03 v38.09,60.8 38.09,65.24 IC22.13 | v63.49,60.16 63.49,55.08 IC21.20 | v78.73,60.16 78.73,65.24 IC23.13 | v102.87,60.16 v102.87,51.27
  Bottom 0.254: 64.13,59.52 v63.49,60.16 | 64.13,59.52 74.29,59.52 74.93,60.16 v78.73,60.16 v102.87,60.16 | v102.87,51.27 105.41,51.27 IC17.31 | v38.09,60.8 38.73,60.16 58.41,60.16 59.05,59.52 64.13,59.52
D3  (via drill 0.61)
  Top 0.254: v40.63,30.95 v40.63,51.91 40.63,55.71 40,56.35 40,64.61 39.36,65.24 39.36,76.67 40.63,77.94 40.63,80.48 IC22.15 | v66.04,48.09 66.04,52.54 IC21.19 | v82.55,47.46 82.55,74.13 81.28,75.4 81.28,80.48 IC23.15
  Bottom 0.254: v40.63,30.95 36.82,30.95 IC24.30 | v40.63,51.91 65.4,51.91 66.04,52.54 IC21.19 | v66.04,48.09 82.55,48.09 | 82.55,48.09 89.53,48.09 90.17,47.46 92.7,47.46 93.98,48.73 105.41,48.73 IC17.30 | 82.55,48.09 v82.55,47.46
D4  (via drill 0.61)
  Top 0.254: v38.09,87.47 38.09,83.02 IC22.16 | v78.73,87.47 78.73,83.02 IC23.16 | v67.31,29.68 v67.31,44.92 67.31,48.09 68.58,49.37 68.58,52.54 IC21.18 68.58,55.08 68.58,56.98 67.94,57.62 67.94,64.61 67.31,65.24 v67.31,87.47
  Bottom 0.254: v38.09,87.47 38.73,88.1 67.31,88.1 | 67.31,88.1 78.1,88.1 v78.73,87.47 | v67.31,29.68 66.67,29.04 56.51,29.04 55.88,28.41 36.82,28.41 IC24.29 | v67.31,44.92 92.7,44.92 93.34,44.28 104.77,44.28 106.04,45.55 IC17.29 | v67.31,87.47 67.31,88.1
D5  (via drill 0.61)
  Top 0.254: IC22.17 35.55,80.48 v35.55,70.32 35.55,69.05 34.28,67.78 34.28,57.62 33.65,56.98 33.65,26.5 34.28,25.87 IC24.28 | v69.84,76.67 v69.84,70.32 69.84,58.25 70.48,57.62 70.48,54.45 IC21.17 | v76.2,76.67 76.2,80.48 IC23.17 | v95.25,75.4 v95.25,47.46
  Bottom 0.254: v69.84,76.67 v76.2,76.67 77.47,76.67 78.73,75.4 v95.25,75.4 | v95.25,47.46 107.95,47.46 108.58,46.82 108.58,45.55 107.31,44.28 IC17.28 | v35.55,70.32 36.19,70.95 65.4,70.95 66.04,70.32 v69.84,70.32
D6  (via drill 0.61)
  Top 0.254: v27.94,23.33 28.57,23.96 28.57,41.74 26.67,43.65 26.67,44.28 27.3,44.92 27.3,64.61 26.67,65.24 26.67,67.78 28.57,69.69 28.57,76.67 29.21,77.3 v29.21,83.66 | v73.66,43.02 73.66,52.54 IC21.16 73.66,55.08 73.66,63.34 72.39,64.61 72.39,67.78 73.66,69.05 73.66,80.48 IC23.18 73.66,83.02 v73.66,86.19 | v33.02,86.19 33.02,83.02 IC22.18
  Bottom 0.254: v27.94,23.33 34.28,23.33 IC24.27 | v29.21,83.66 32.38,83.66 33.02,83.02 IC22.18 | v73.66,43.02 74.29,43.65 86.36,43.65 87.62,42.38 92.7,42.38 93.34,41.74 106.04,41.74 IC17.27 | v33.02,86.19 38.09,86.19 39.36,87.47 66.04,87.47 67.31,86.19 v73.66,86.19
D7  (via drill 0.61)
  Top 0.254: v29.21,20.79 29.21,43.65 28.57,44.28 28.57,64.61 29.21,65.24 29.21,76.03 30.48,77.3 30.48,80.48 IC22.19 30.48,83.02 v30.48,84.92 | v77.47,75.4 77.47,55.08 76.83,54.45 IC21.15 76.2,52.54 v76.2,41.74 | v71.12,75.4 71.12,80.48 IC23.19 71.12,83.02 v71.12,84.92
  Bottom 0.254: v29.21,20.79 34.28,20.79 IC24.26 | v71.12,75.4 v77.47,75.4 | v76.2,41.74 76.83,41.11 88.9,41.11 90.17,39.84 92.7,39.84 93.34,39.2 106.04,39.2 IC17.26 | v30.48,84.92 33.02,84.92 33.65,85.56 38.73,85.56 40,86.83 65.4,86.83 66.67,85.56 70.48,85.56 v71.12,84.92
E  (via drill 0.61)
  Top 0.254: v74.29,22.06 74.29,34.12 77.47,37.3 77.47,48.09 78.73,49.37 78.73,52.54 IC21.14 78.73,55.08 78.73,57.62 80.01,58.89 v80.01,62.7 | v113.03,10.63 112.39,11.27 112.39,21.42 v113.03,22.06 | v104.77,62.7 104.77,65.88 105.41,66.51 IC17.37
  Bottom 0.254: IC24.25 36.19,18.88 50.16,18.88 50.79,19.52 52.7,19.52 55.24,22.06 56.51,22.06 57.14,21.42 71.12,21.42 71.75,22.06 v74.29,22.06 85.09,22.06 85.72,22.7 98.42,22.7 99.06,22.06 v113.03,22.06 | v113.03,10.63 115.56,10.63 IC18.10 | v80.01,62.7 v104.77,62.7
GND  (via drill 0.61)
  Top 0.508: IC24.1 20.32,56.98 20.32,58.25 BYP24.2 | BYP25.2 10.15,58.25 v10.15,53.81 v10.15,33.49 10.15,31.58 BYP26.2 10.15,30.31 v10.15,25.87 10.15,18.25 9.52,17.61 9.52,6.18 8.88,5.55 IC26.10 | v5.08,58.89 5.08,76.03 BYP22.2 | X1.5 47.62,16.34 47.62,17.61 48.25,18.25 48.25,20.15 BYP20.2 | R13.1 41.27,57.62 40.63,58.25 40.63,65.24 IC22.14 40,67.14 40,76.03 v40.63,76.67 | v53.34,43.65 53.34,39.84 IC21.1 53.34,37.3 53.34,36.66 52.7,36.03 52.7,35.39 51.43,34.12 IC20.15 50.79,32.22 50.79,30.95 52.06,29.68 52.06,23.96 51.43,23.33 C11.2 50.79,22.7 50.79,21.42 C7.2 50.79,20.15 v50.79,18.25 | v55.88,43.65 55.88,52.54 IC21.23 | v46.98,43.65 v46.98,57.62 | v71.12,36.03 72.39,34.76 72.39,28.41 71.75,27.77 v71.75,25.87 | v79.37,8.09 79.37,13.17 78.73,13.81 78.73,25.23 BYP27.2 | v66.04,8.09 66.04,12.54 X1.G1 66.04,16.34 v66.04,18.25 | C6.2 91.44,6.18 91.44,7.46 C4.2 | v93.98,8.09 93.98,10 C5.2 | JP1.1 109.22,4.28 109.22,4.92 IC18.7 110.48,5.55 111.12,6.18 111.12,10 111.76,10.63 111.76,25.23 IC19.8 113.03,25.87 113.66,26.5 113.66,32.85 114.3,33.49 114.3,49.37 | v101.59,5.55 101.59,3.64 C3.2 | v81.28,74.13 81.28,67.78 IC23.14 | BYP17.2 106.68,23.96 106.68,25.23 IC17.21 | IC28.13 119.38,59.52 119.38,60.8 IC28.14 119.38,62.06 119.38,63.34 IC28.15 | 114.3,49.37 v114.93,48.73 | 114.3,49.37 v114.3,58.89 114.3,70.95 C1.1 | v102.87,70.32 v102.87,74.13 | v20.32,2.38 20.32,4.28 JP3.1 | v40.63,2.38 40.63,12.54 X1.G2
  Bottom 0.508: v10.15,53.81 13.96,53.81 IC25.19 16.51,53.81 17.78,53.81 19.68,55.71 IC24.1 | v5.08,58.89 9.52,58.89 BYP25.2 | IC26.10 8.25,4.92 8.88,4.28 20.32,4.28 JP3.1 | CORE-IO.9 3.17,33.49 4.44,33.49 CORE-IO.10 5.71,33.49 6.34,33.49 IC25.10 8.88,33.49 v10.15,33.49 | v10.15,25.87 13.96,25.87 IC26.19 | BYP20.2 48.89,20.79 50.16,20.79 C7.2 | X1.5 47.62,15.71 42.54,15.71 X1.G2 | v40.63,76.67 45.08,76.67 BYP23.2 | v55.88,43.65 v53.34,43.65 51.43,43.65 BYP21.2 50.16,43.65 v46.98,43.65 | v46.98,57.62 42.54,57.62 R13.1 | v71.12,36.03 64.77,36.03 63.49,34.76 IC20.10 | v71.75,25.87 78.1,25.87 BYP27.2 | v66.04,8.09 74.93,8.09 IC27.7 77.47,8.09 v79.37,8.09 80.64,6.82 87.62,6.82 88.9,5.55 90.8,5.55 C6.2 92.07,5.55 v101.59,5.55 106.04,5.55 BYP18.2 107.31,5.55 107.95,5.55 IC18.7 | v93.98,8.09 92.07,8.09 C4.2 | v81.28,74.13 90.17,74.13 IC17.1 92.7,74.13 v102.87,74.13 | IC17.21 107.95,25.87 108.58,25.87 BYP19.2 109.85,25.87 110.48,25.87 IC19.8 | C1.1 113.66,71.59 112.39,71.59 C2.2 111.12,71.59 109.85,71.59 109.22,70.95 108.58,70.95 107.95,70.32 v102.87,70.32 | BYP28.2 109.85,48.73 110.48,48.73 IC28.8 113.03,48.73 v114.93,48.73 | v114.3,58.89 118.11,58.89 IC28.13 | v50.79,18.25 v66.04,18.25 | v20.32,2.38 20.95,1.74 40,1.74 v40.63,2.38
HLT\
  Top 0.254: IC17.2 92.07,72.22 93.34,73.5 93.34,75.4 92.7,76.03 92.7,77.3 93.98,78.58 R5.1
IO-E\  (via drill 0.61)
  Top 0.254: v60.95,11.9 v60.95,19.52
  Bottom 0.254: v60.95,11.9 60.32,11.27 45.71,11.27 45.08,11.9 44.45,11.9 43.81,11.27 39.36,11.27 38.73,11.9 36.82,11.9 36.19,12.54 IC24.23 | v60.95,19.52 67.31,19.52 72.39,14.44 80.01,14.44 81.91,16.34 81.91,19.52 113.03,19.52 118.74,25.23 IC19.9
IO-F\  (via drill 0.61)
  Top 0.254: v73.02,27.14 73.66,27.77 73.66,37.3 IC21.9
  Bottom 0.254: v73.02,27.14 108.58,27.14 109.85,28.41 110.48,28.41 IC19.7
IRQ\  (via drill 0.61)
  Top 0.254: IC24.38 35.55,50.63 35.55,49.37 IC24.37 | v43.17,48.73 43.17,83.66 R7.1 | v88.26,83.66 88.26,79.21 88.9,78.58 88.9,71.59 89.53,70.95 89.53,67.14 90.17,66.51 IC17.4
  Bottom 0.254: v43.17,48.73 36.82,48.73 IC24.37 | v88.26,83.66 71.12,83.66 69.84,84.92 66.04,84.92 64.77,86.19 46.98,86.19 45.08,84.29 43.81,84.29 R7.1
MR
  Top 0.254: IC17.3 92.07,69.69 93.98,71.59 93.98,76.03 R8.1
N$3
  Top 0.254: IC17.39 107.95,71.59 111.76,75.4 111.76,76.03 C2.1
  Bottom 0.254: Q1.1 118.74,71.59 114.93,75.4 113.66,75.4 112.39,76.67 C2.1
N$4
  Top 0.254: IC17.38 107.31,69.69 113.66,76.03 113.66,76.67 C1.2 114.93,76.67 118.74,76.67 Q1.2
N$5
  Top 0.254: IC25.18 16.51,51.27 19.05,53.81 IC24.2
N$6
  Top 0.254: IC18.5 108.58,11.27 108.58,12.54 IC18.4 108.58,13.81 108.58,15.08 IC18.3
N$21
  Top 0.254: R1.1 107.31,20.79 107.95,20.79 IC18.1
  Bottom 0.254: C3.1 102.23,13.17 103.5,11.9 110.48,11.9 113.03,9.36 122.55,9.36 125.73,12.54 125.73,27.14 118.11,27.14 116.2,25.23 116.2,23.96 113.03,20.79 110.48,20.79 IC18.1
N$22
  Top 0.254: IC18.2 107.95,18.25 107.31,18.25 R2.1 106.68,17.61 105.41,16.34 105.41,4.28 106.04,3.64 JP1.2
N$23
  Top 0.254: IC21.3 59.05,37.94 60.32,37.94 IC21.4
  Bottom 0.254: IC27.5 74.93,13.17 69.21,13.17 67.31,11.27 64.13,11.27 60.32,15.08 60.32,16.98 43.17,16.98 42.54,17.61 37.46,17.61 36.82,16.98 31.75,16.98 26.67,22.06 26.67,34.76 46.98,34.76 47.62,35.39 55.24,35.39 57.78,37.94 IC21.3
N$24
  Top 0.254: IC26.18 15.87,23.96 17.14,25.23 17.14,30.31 19.68,32.85 IC24.10
N$25
  Top 0.254: IC26.17 15.87,21.42 17.78,23.33 17.78,28.41 19.68,30.31 IC24.11
N$27
  Top 0.254: IC27.2 75.56,20.15 74.29,18.88 R11.A 73.66,16.98 71.12,14.44 71.12,11.9 R11.S 71.75,10.63 74.93,10.63 IC27.6
  Bottom 0.254: C6.1 85.72,5.55 84.45,4.28 79.37,4.28 76.83,6.82 74.93,6.82 74.29,7.46 66.67,7.46 66.04,6.82 64.77,8.09 64.77,10 70.48,10 R11.S
N$28
  Top 0.254: IC27.1 76.83,22.7 78.1,21.42 78.1,6.82 76.83,5.55 R9.1
  Bottom 0.254: R9.1 76.83,5.55 79.37,3.01 83.18,3.01 R10.2
N$94
  Top 0.254: IC26.16 15.87,18.88 18.41,21.42 18.41,26.5 19.68,27.77 IC24.12
N$124
  Bottom 0.254: IC26.15 15.87,16.34 18.41,18.88 18.41,25.87 19.05,25.87 IC24.13
N$125
  Top 0.254: IC26.14 15.87,13.81 19.05,16.98 22.22,16.98 22.22,21.42 20.95,22.7 IC24.14
N$126
  Bottom 0.254: IC26.13 16.51,10.63 17.78,11.9 21.59,11.9 22.22,12.54 22.22,20.15 20.95,20.15 IC24.15
N$127
  Top 0.254: IC26.12 14.6,8.73 13.33,10 13.33,16.34 13.96,16.98 17.78,16.98 19.05,18.25 IC24.16
N$128
  Bottom 0.254: IC26.11 14.6,6.18 13.33,7.46 13.33,14.44 17.78,14.44 19.05,15.71 IC24.17
N$129
  Top 0.254: IC25.17 16.51,48.73 19.05,51.27 IC24.3
N$130
  Top 0.254: IC25.16 16.51,46.19 19.05,48.73 IC24.4
N$131
  Top 0.254: IC25.15 16.51,43.65 19.05,46.19 IC24.5
N$132
  Top 0.254: IC25.14 16.51,41.11 19.05,43.65 IC24.6
N$133
  Top 0.254: IC25.13 16.51,38.57 19.05,41.11 IC24.7
N$134
  Top 0.254: IC25.12 16.51,36.03 19.05,38.57 IC24.8
N$135
  Top 0.254: IC25.11 16.51,33.49 19.05,36.03 IC24.9
N$136
  Bottom 0.254: IC24.19 21.59,10.63 22.86,11.9 22.86,27.14 10.15,27.14 8.88,28.41 IC26.1
N$137  (via drill 0.61)
  Top 0.254: v23.49,57.62 v23.49,53.81
  Bottom 0.254: v23.49,57.62 13.96,57.62 13.33,56.98 8.25,56.98 IC25.1 | v23.49,53.81 34.28,53.81 IC24.39
N$138  (via drill 0.61)
  Top 0.254: v45.71,54.45 45.71,34.76 43.81,32.85 43.81,24.6 44.45,23.96 v44.45,10.63
  Bottom 0.254: v45.71,54.45 37.46,54.45 36.19,55.71 IC24.40 | v44.45,10.63 68.58,10.63 70.48,12.54 74.29,12.54 74.93,11.9 77.47,11.9 78.1,11.27 80.01,11.27 80.64,10.63 82.55,10.63 IC27.9
N$140
  Top 0.254: C4.1 85.72,8.09 85.09,8.09 IC27.8 83.18,8.73 81.91,10 81.91,16.34 83.18,17.61 IC27.12
  Bottom 0.254: R4.1 90.8,10.63 88.26,8.09 86.99,8.09 C4.1
N$141
  Top 0.254: IC27.13 85.09,20.79 88.9,20.79 88.9,18.88 R3.1
  Bottom 0.254: R3.1 89.53,18.25 90.8,18.25 R4.2
N$142
  Bottom 0.254: IC27.11 85.09,15.71 93.34,15.71 C5.1
N$143
  Bottom 0.254: R10.1 75.56,3.01 74.29,4.28 73.66,4.28 R11.E
N$144
  Bottom 0.254: X1.4 50.79,15.08 51.43,14.44 56.51,14.44 57.14,13.81 X1.6
N$145
  Top 0.254: X1.8 52.7,13.17 53.97,13.17 X1.7
N$147  (via drill 0.61)
  Top 0.254: IC18.12 116.84,16.34 116.84,17.61 IC18.13 115.56,18.25 114.93,18.88 v114.93,23.96 | v67.94,24.6 67.94,26.5 64.77,29.68 64.77,37.3 64.13,37.94 IC21.5
  Bottom 0.254: v67.94,24.6 85.09,24.6 85.72,23.96 98.42,23.96 99.06,24.6 107.31,24.6 107.95,23.96 v114.93,23.96
N$148
  Top 0.254: LED1.K 119.38,11.27 118.11,12.54 118.11,13.17 IC18.11
N$149
  Bottom 0.254: R12.1 86.99,18.25 88.26,16.98 110.48,16.98 115.56,11.9 120.01,11.9 121.28,10.63 LED1.A
N$150
  Top 0.254: IC21.24 53.34,55.08 53.34,56.35 JP2.1
  Bottom 0.254: R13.2 50.16,57.62 52.7,57.62 JP2.1
N$151
  Top 0.254: IC18.8 117.47,6.18 120.65,9.36 120.65,22.06 117.47,25.23 117.47,70.32 114.93,72.86 113.03,72.86 113.03,66.51 IC28.1
N$152
  Top 0.254: IC19.5 112.39,34.12 113.66,35.39 113.66,56.98 112.39,58.25 IC28.4
N$153
  Top 0.254: IC20.7 64.13,25.23 65.4,25.23 IC20.8
N$154
  Bottom 0.254: C7.1 56.51,20.79 73.66,20.79 75.56,18.88 IC27.3
N$155  (via drill 0.61)
  Top 0.254: v58.41,30.95 58.41,27.14 IC20.5 | v68.58,30.95 68.58,32.85 C9.2
  Bottom 0.254: v58.41,30.95 v68.58,30.95
N$156
  Bottom 0.254: IC20.4 56.51,26.5 58.41,28.41 67.94,28.41 C9.1
N$157
  Bottom 0.254: C8.2 45.08,30.95 43.81,29.68 34.28,29.68 33.65,29.04 33.65,27.14 46.98,27.14 47.62,27.77 51.43,27.77 52.7,26.5 IC20.3
N$158
  Top 0.254: C8.1 46.35,25.87 47.62,25.87 IC20.1
N$159
  Bottom 0.254: C11.1 56.51,23.33 57.14,23.96 59.05,23.96 60.32,25.23 IC20.6
N$160
  Bottom 0.254: C10.2 48.89,23.33 50.16,24.6 50.79,24.6 IC20.2
NMI\  (via drill 0.61)
  Top 0.254: IC17.6 90.17,61.43 89.53,61.43 R6.1 88.9,60.8 88.9,57.62 87.62,56.35 87.62,53.17 88.26,52.54 88.26,44.28 v87.62,43.65 | v68.58,43.65 68.58,39.84 IC21.7
  Bottom 0.254: v68.58,43.65 69.21,44.28 86.99,44.28 v87.62,43.65
PIA-A0
  Top 0.254: IC25.2 6.98,53.17 2.54,48.73 2.54,44.28 CORE-IO.1
PIA-A1
  Top 0.254: IC25.3 6.98,50.63 5.08,48.73 5.08,44.28 CORE-IO.2
PIA-A2
  Bottom 0.254: IC25.4 6.98,48.09 3.81,44.92 3.81,43.02 2.54,41.74 CORE-IO.3
PIA-A3
  Top 0.254: IC25.5 8.25,45.55 9.52,44.28 9.52,43.02 8.88,42.38 5.08,42.38 5.08,41.74 CORE-IO.4
PIA-A4
  Bottom 0.254: IC25.6 8.25,43.02 9.52,41.74 9.52,39.84 4.44,39.84 3.17,38.57 CORE-IO.5
PIA-A5
  Top 0.254: IC25.7 6.98,40.48 5.71,39.2 5.71,38.57 CORE-IO.6
PIA-A6
  Bottom 0.254: IC25.8 6.98,37.94 6.34,37.3 4.44,37.3 3.17,36.03 CORE-IO.7
PIA-A7
  Top 0.254: IC25.9 6.34,36.03 5.71,36.03 CORE-IO.8
PIA-B0
  Bottom 0.254: IC26.2 6.98,26.5 6.34,27.14 4.44,27.14 3.17,28.41 CORE-IO.13
PIA-B1
  Top 0.254: IC26.3 6.98,22.7 6.34,22.7 5.71,22.06 4.44,22.06 3.81,22.7 3.81,26.5 5.08,27.77 CORE-IO.14
PIA-B2
  Bottom 0.254: IC26.4 6.98,20.15 6.34,19.52 4.44,19.52 3.81,20.15 3.81,25.23 2.54,25.23 CORE-IO.15
PIA-B3
  Top 0.254: IC26.5 8.25,18.88 9.52,20.15 9.52,23.96 8.88,24.6 5.08,24.6 5.08,25.23 CORE-IO.16
PIA-B4  (via drill 0.61)
  Top 0.254: v3.81,15.71 3.81,21.42 3.17,22.06 3.17,23.33 CORE-IO.17
  Bottom 0.254: v3.81,15.71 6.34,15.71 IC26.6
PIA-B5
  Bottom 0.254: IC26.7 8.25,13.81 9.52,15.08 9.52,22.06 5.71,22.06 5.08,22.7 CORE-IO.18
PIA-B6
  Bottom 0.254: IC26.8 6.98,11.27 2.54,15.71 2.54,20.15 CORE-IO.19
PIA-B7
  Top 0.254: IC26.9 6.98,8.73 5.08,10.63 5.08,20.15 CORE-IO.20
R/W\  (via drill 0.61)
  Top 0.254: v81.28,57.62 81.28,55.08 IC21.13 81.28,52.54 v81.28,46.82 | 32.38,47.46 32.38,64.61 31.75,65.24 v31.75,70.32 | 32.38,47.46 32.38,39.84 31.11,38.57 33.02,36.66 33.02,10.63 34.28,9.36 34.28,8.09 IC24.21 | v10.15,69.69 10.15,80.48 IC22.27 | 32.38,47.46 v31.75,47.46
  Bottom 0.254: v81.28,57.62 100.96,57.62 102.23,58.89 105.41,58.89 IC17.34 | v31.75,70.32 31.11,69.69 v10.15,69.69 | v81.28,46.82 80.64,46.19 68.58,46.19 67.94,46.82 65.4,46.82 64.77,47.46 v31.75,47.46
RST\  (via drill 0.61)
  Top 0.254: v62.22,41.74 62.22,72.86 63.49,74.13 64.77,74.13 v64.77,72.86 | v103.5,8.09 104.14,8.73 104.14,28.41 99.69,32.85 99.69,44.92 99.06,45.55 99.06,50 98.42,50.63 98.42,62.7 99.69,63.97 v99.69,72.86
  Bottom 0.254: v62.22,41.74 61.59,41.11 36.82,41.11 IC24.34 | v64.77,72.86 v99.69,72.86 102.87,72.86 104.14,74.13 105.41,74.13 IC17.40 | v103.5,8.09 107.95,8.09 IC18.6
RX
  Top 0.254: IC20.12 58.41,34.76 55.88,37.3 IC21.2
RXD
  Top 0.254: IC20.13 55.88,32.22 54.6,30.95 54.6,17.61 53.34,16.34 X1.3
TX
  Bottom 0.254: IC20.11 61.59,34.12 65.4,37.94 IC21.6
TXD
  Top 0.254: IC20.14 53.97,34.12 55.24,35.39 56.51,35.39 57.14,34.76 57.14,16.98 56.51,16.34 X1.2
VCC  (via drill 0.61)
  Top 0.508: IC25.20 15.23,56.98 15.23,58.25 BYP25.1 | IC26.20 15.23,29.04 15.23,30.31 BYP26.1 | v11.42,55.71 11.42,31.58 v12.06,30.95 | v17.78,8.09 17.78,6.18 R14.2 | IC24.22 34.28,10.63 33.65,11.27 33.65,15.08 34.28,15.71 IC24.24 36.82,15.71 38.09,16.98 v38.09,20.79 | BYP20.1 43.17,21.42 43.17,22.7 C10.1 43.17,23.96 v43.17,33.49 | IC20.16 48.25,34.76 v48.25,38.57 v48.25,63.34 48.25,65.24 IC23.1 48.25,67.78 v48.25,78.58 48.25,80.48 IC23.28 | R7.2 50.79,83.66 50.79,83.02 IC23.27 | v12.69,79.21 12.69,80.48 IC22.26 | v25.39,63.34 25.39,59.52 BYP24.1 | R5.2 101.59,78.58 101.59,77.3 R8.2 101.59,76.03 v101.59,63.97 v101.59,56.98 | IC17.36 106.68,63.34 106.68,62.06 IC17.35 107.95,61.43 109.22,60.16 109.22,54.45 BYP28.1 | v124.45,20.79 125.09,20.79 125.09,43.65 | 125.09,43.65 125.09,65.88 v124.45,66.51 | 125.09,43.65 v124.45,43.65 | v88.9,56.35 88.9,54.45 R6.2 88.9,53.17 v88.9,39.84 | v80.64,5.55 v80.64,13.17 80.01,13.81 v80.01,15.71 v80.01,23.33 | v86.36,13.17 86.36,11.27 R12.2 | v99.06,10.63 99.06,17.61 R2.2 99.06,18.88 99.06,20.15 R1.2 99.06,21.42 v99.06,23.33 | v72.39,41.11 72.39,39.84 71.75,39.2 IC21.8 | IC27.14 83.81,23.96 83.81,25.23 BYP27.1 | v101.59,29.68 101.59,23.96 BYP17.1 | v81.28,25.87 81.28,37.3 IC21.12 | v50.79,36.66 50.79,37.94 BYP21.1 | v54.6,36.66 54.6,55.08 55.24,55.71 55.24,56.98 JP2.2
  Bottom 0.508: BYP24.1 24.76,58.89 22.22,58.89 20.95,60.16 18.41,60.16 17.14,58.89 15.87,58.89 BYP25.1 | CORE-IO.11 3.17,30.95 4.44,30.95 CORE-IO.12 5.71,30.95 7.62,30.95 8.25,30.31 8.88,30.31 10.79,28.41 13.96,28.41 IC26.20 | v11.42,55.71 12.06,56.35 13.96,56.35 IC25.20 | v12.06,30.95 14.6,30.95 BYP26.1 | v17.78,8.09 19.05,8.09 IC24.20 21.59,8.09 28.57,8.09 31.11,10.63 34.28,10.63 IC24.22 | v48.25,38.57 50.16,38.57 BYP21.1 | v43.17,33.49 47.62,33.49 IC20.16 | BYP22.1 5.71,81.75 6.98,81.75 IC22.28 7.62,83.02 8.25,83.66 12.06,83.66 12.69,83.02 IC22.26 | BYP23.1 46.35,81.75 47.62,81.75 IC23.28 48.89,81.75 50.16,81.75 IC23.27 | v12.69,79.21 47.62,79.21 v48.25,78.58 | v38.09,20.79 42.54,20.79 BYP20.1 | v25.39,63.34 26.03,63.97 47.62,63.97 v48.25,63.34 | v101.59,63.97 105.41,63.97 IC17.36 107.31,64.61 107.95,65.24 113.03,65.24 113.66,65.88 114.93,65.88 115.56,66.51 118.11,66.51 IC28.16 120.65,66.51 v124.45,66.51 | v124.45,20.79 118.11,20.79 IC18.14 | v124.45,43.65 120.65,43.65 IC19.16 | JP2.2 55.88,56.35 v88.9,56.35 90.17,56.35 IC17.8 92.07,56.98 v101.59,56.98 | R12.2 86.99,10.63 88.26,10.63 R3.2 | v80.64,5.55 83.18,5.55 R9.2 | v80.64,13.17 82.55,13.17 IC27.10 85.09,13.17 v86.36,13.17 | v80.01,15.71 77.47,15.71 IC27.4 | v99.06,10.63 106.04,10.63 BYP18.1 | v72.39,41.11 73.02,40.48 76.2,40.48 | 76.2,40.48 76.2,39.84 IC21.10 | 80.64,40.48 81.28,39.84 IC21.12 | 80.64,40.48 76.2,40.48 | BYP17.1 100.96,23.33 v99.06,23.33 85.09,23.33 IC27.14 82.55,23.33 v80.01,23.33 | v101.59,29.68 108.58,29.68 109.22,30.31 BYP19.1 | v81.28,25.87 83.18,25.87 BYP27.1 | v88.9,39.84 88.26,40.48 80.64,40.48
  Bottom 0.508: v50.79,36.66 v54.6,36.66
VMA  (via drill 0.61)
  Top 0.254: v100.33,9.36 100.33,25.87 99.69,26.5 99.69,31.58 99.06,32.22 99.06,44.28 98.42,44.92 98.42,49.37 97.79,50 97.79,63.34 v98.42,63.97
  Bottom 0.254: v100.33,9.36 111.76,9.36 113.03,8.09 115.56,8.09 IC18.9 | v98.42,63.97 92.7,63.97 IC17.5

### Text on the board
tPlace: Core Board | +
